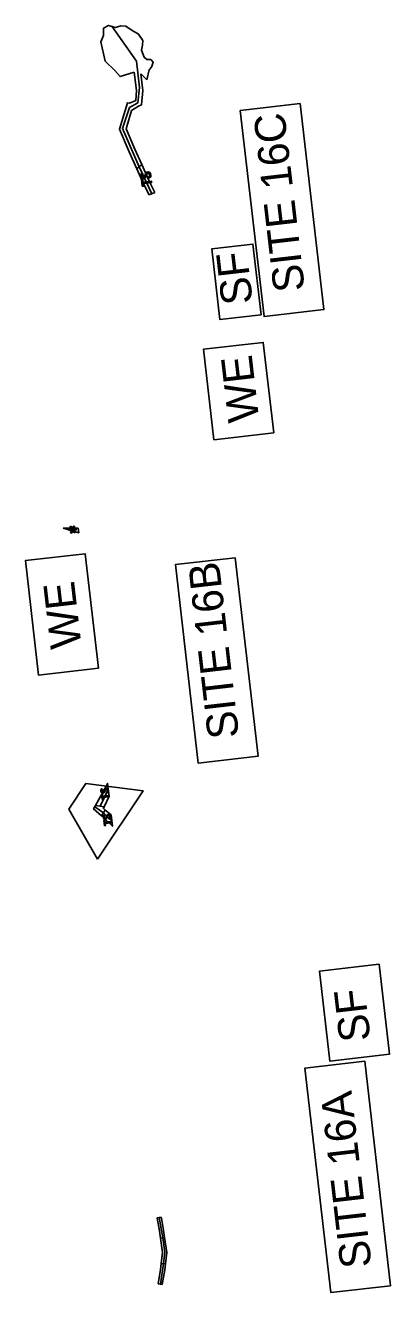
# Model space of a CAD drawing. Extents: x 474218 to 481634, y 484357 to 504997.
# Drawn here: x 478282 to 478459, y 495986 to 496599 of the extents above; entities that cross this region are included whole.
import ezdxf

# ---------------------------------------------------------------- set-up
doc = ezdxf.new("R2010")
doc.units = 0
for name, color, linetype in [('Exist Hydro Jurisdictional Stream or Body of Water', 7, 'Continuous'), ('Old_Level_29', 7, 'Continuous'), ('Old_Level_30', 7, 'Continuous'), ('Prop Boundary Clearing Mechanized Hatching CELL', 7, 'Continuous'), ('Prop Earthen Structure Impacts In Surface Waters Hatching CELL', 7, 'Continuous'), ('Prop Grid Mask', 7, 'Continuous'), ('Scratch_Level_4', 7, 'Continuous'), ('Temp Earthen Structure Impacts In Surface Waters Hatching CELL', 7, 'Continuous')]:
    doc.layers.add(name, color=color, linetype=linetype)

msp = doc.modelspace()

# ---------------------------------------------------------------- linework, layer by layer
at = {"layer": 'Exist Hydro Jurisdictional Stream or Body of Water'}
for points in [[(478376.47, 496456.35), (478372.53, 496490.56), (478392.45, 496492.85), (478396.39, 496458.64)], [(478429.6, 496097.83), (478424.59, 496141.27), (478453.48, 496144.61), (478458.49, 496101.17)]]:
    msp.add_lwpolyline(points, close=True, dxfattribs=at)
at = {"layer": 'Old_Level_29'}
for points in [[(478397.84, 496457.83), (478386.35, 496557.43), (478415.25, 496560.76), (478426.74, 496461.16)], [(478366.04, 496241.85), (478354.97, 496337.87), (478383.87, 496341.2), (478394.94, 496245.18)], [(478430.14, 495985.85), (478417.61, 496094.47), (478446.51, 496097.8), (478459.04, 495989.18)]]:
    msp.add_lwpolyline(points, close=True, dxfattribs=at)
at = {"layer": 'Old_Level_30'}
for points in [[(478373.6, 496398.29), (478368.56, 496442.01), (478397.45, 496445.34), (478402.49, 496401.62)], [(478288.84, 496284.41), (478282.45, 496339.82), (478311.34, 496343.16), (478317.73, 496287.74)]]:
    msp.add_lwpolyline(points, close=True, dxfattribs=at)
at = {"layer": 'Prop Boundary Clearing Mechanized Hatching CELL'}
for p, q in [((478300.65, 496355.5), (478308.23, 496353.27)), ((478307.98, 496355.43), (478300.65, 496355.5)), ((478308.23, 496353.27), (478307.98, 496355.43))]:
    msp.add_line(p, q, dxfattribs=at)
for points in [[(478304.79, 496354.47), (478304.84, 496354.48), (478304.77, 496355.05), (478304.72, 496355.04), (478303.62, 496354.98), (478303.7, 496354.3)], [(478304.77, 496355.07), (478304.79, 496355.05), (478304.65, 496356.28), (478304.63, 496356.31), (478304.56, 496356.4), (478304.01, 496355.99), (478304.71, 496355.15)], [(478305.42, 496354.22), (478305.45, 496354.27), (478305.31, 496355.43), (478305.29, 496355.37), (478304.65, 496356.28), (478304.79, 496355.05), (478304.77, 496355.05), (478304.84, 496354.48), (478304.8, 496354.39), (478304.32, 496353.4), (478304.32, 496353.39), (478304.94, 496353.12), (478304.99, 496353.22), (478305, 496353.25)], [(478306.02, 496353.4), (478306.12, 496353.26), (478305.98, 496354.48), (478305.89, 496354.59), (478305.82, 496355.17), (478305.81, 496355.17), (478305.67, 496356.35), (478305.31, 496355.43), (478305.45, 496354.27), (478306.01, 496353.43)], [(478305.88, 496355.31), (478306.36, 496356.25), (478305.74, 496356.53), (478305.67, 496356.35), (478305.81, 496355.17)], [(478306.55, 496354.64), (478307.06, 496354.67), (478306.98, 496355.36), (478306.48, 496355.28), (478306.47, 496355.28), (478305.9, 496355.18), (478305.82, 496355.17), (478305.89, 496354.59), (478305.97, 496354.6), (478306.55, 496354.64)], [(478306.66, 496353.66), (478306.66, 496353.67), (478306.66, 496353.67), (478305.98, 496354.48), (478306.12, 496353.26)]]:
    msp.add_lwpolyline(points, close=True, dxfattribs=at)
at = {"layer": 'Prop Earthen Structure Impacts In Surface Waters Hatching CELL'}
for p, q in [((478338.24, 496575.16), (478341.19, 496572.34)), ((478333.82, 496557.47), (478337.16, 496559.59)), ((478336.34, 496529.2), (478338.68, 496531.3)), ((478349.76, 496012.52), (478347.78, 496012.24)), ((478348.15, 495999.88), (478350.16, 495999.86))]:
    msp.add_line(p, q, dxfattribs=at)
for points in [[(478341.19, 496572.34), (478342.33, 496577.12), (478343.44, 496578.45), (478344.2, 496580.76), (478343.07, 496582.04), (478341.17, 496582.07), (478339.84, 496583.18), (478338.66, 496586.7), (478339.05, 496589.05), (478339.25, 496591.23), (478337.2, 496594.43), (478333.53, 496596.42), (478331.09, 496598.22), (478328.54, 496598.45), (478326.03, 496597.51), (478322.68, 496598.62), (478320.17, 496597.2), (478320.15, 496593.76), (478318.87, 496590.61), (478321.06, 496581.27), (478325.78, 496576.8), (478328.26, 496573.82), (478335.11, 496575.92)], [(478335.11, 496575.92), (478336.25, 496567.12), (478335.81, 496562.27), (478332.74, 496560.94)], [(478337.16, 496559.59), (478338.63, 496560.22), (478339.27, 496567.18), (478338.24, 496575.16)], [(478332.74, 496560.94), (478331.83, 496561.22), (478327.95, 496548.46), (478332.63, 496537.53), (478336.34, 496529.2)], [(478338.68, 496531.3), (478335.38, 496538.74), (478331.14, 496548.63), (478333.82, 496557.47)], [(478333.82, 496557.47), (478333.82, 496557.47), (478333.82, 496557.47)], [(478337.16, 496559.59), (478337.16, 496559.59), (478337.16, 496559.59), (478337.16, 496559.59)], [(478319.27, 496216.43), (478321.11, 496219.19), (478320.19, 496219.93), (478320.6, 496220.83), (478316.32, 496221.36), (478315.44, 496219.76), (478319.27, 496216.43)], [(478347.78, 496012.24), (478348.78, 496005.25), (478348.15, 495999.88)], [(478350.16, 495999.86), (478350.8, 496005.28), (478349.76, 496012.52)]]:
    msp.add_lwpolyline(points, dxfattribs=at)
at = {"layer": 'Prop Grid Mask'}
for points in [[(478426.74, 496461.16), (478415.25, 496560.76), (478386.35, 496557.43), (478397.84, 496457.83)], [(478396.39, 496458.64), (478392.45, 496492.85), (478372.53, 496490.56), (478376.47, 496456.35)], [(478402.49, 496401.62), (478397.45, 496445.34), (478368.56, 496442.01), (478373.6, 496398.29)], [(478317.73, 496287.74), (478311.34, 496343.16), (478282.45, 496339.82), (478288.84, 496284.41)], [(478394.94, 496245.18), (478383.87, 496341.2), (478354.97, 496337.87), (478366.04, 496241.85)], [(478458.49, 496101.17), (478453.48, 496144.61), (478424.59, 496141.27), (478429.6, 496097.83)], [(478459.04, 495989.18), (478446.51, 496097.8), (478417.61, 496094.47), (478430.14, 495985.85)]]:
    msp.add_lwpolyline(points, close=True, dxfattribs=at)
at = {"layer": 'Scratch_Level_4'}
for p, q in [((478336.21, 496581.35), (478324.23, 496598.15)), ((478337.71, 496568.53), (478336.21, 496581.35)), ((478343.61, 496517.22), (478337.45, 496530.22)), ((478318.58, 496221.07), (478322.52, 496229.19)), ((478315.96, 496220.72), (478320.18, 496217.82)), ((478320.18, 496217.82), (478324.28, 496213.88)), ((478348.87, 496012.39), (478347.13, 496022.19)), ((478347.73, 495989.97), (478349.21, 495999.87))]:
    msp.add_line(p, q, dxfattribs=at)
for points in [[(478337.45, 496530.22), (478329.4, 496548.75), (478332.81, 496558.84), (478336.78, 496561.1), (478337.71, 496568.53)], [(478349.21, 495999.87), (478349.8, 496005.44), (478348.87, 496012.39)]]:
    msp.add_lwpolyline(points, dxfattribs=at)
for points in [[(478300.65, 496355.5), (478308.23, 496353.27), (478307.98, 496355.43)], [(478317.26, 496195.39), (478339.37, 496228.56), (478311.64, 496232.03), (478303.4, 496219.66)], [(478319.27, 496216.43), (478321.11, 496219.19), (478320.19, 496219.93), (478320.6, 496220.83), (478316.32, 496221.36), (478315.44, 496219.76)]]:
    msp.add_lwpolyline(points, close=True, dxfattribs=at)
at = {"layer": 'Temp Earthen Structure Impacts In Surface Waters Hatching CELL'}
for p, q in [((478338.68, 496531.3), (478336.34, 496529.2)), ((478342.25, 496516.6), (478344.98, 496517.84)), ((478349.76, 496012.52), (478349.13, 496016.99)), ((478347.78, 496012.24), (478349.76, 496012.52))]:
    msp.add_line(p, q, dxfattribs=at)
for points in [[(478344.98, 496517.84), (478342.24, 496523.3), (478338.68, 496531.3)], [(478336.34, 496529.2), (478339.53, 496522.02), (478342.25, 496516.6)], [(478316.32, 496221.36), (478320.6, 496220.83), (478322.89, 496225.95), (478322.19, 496232.07), (478321.44, 496230.72), (478316.32, 496221.36)], [(478319.27, 496216.43), (478320.78, 496215.12), (478324.57, 496211.37), (478323.94, 496216.84), (478321.11, 496219.19), (478319.27, 496216.43)], [(478349.13, 496016.99), (478348.39, 496020.84), (478348.1, 496022.35), (478346.13, 496022.02), (478346.35, 496020.86), (478347.15, 496016.66), (478347.78, 496012.24)], [(478348.65, 495989.81), (478349.81, 495996.83), (478350.16, 495999.86), (478348.15, 495999.88), (478347.83, 495997.11), (478346.68, 495990.14), (478348.65, 495989.81)]]:
    msp.add_lwpolyline(points, dxfattribs=at)
for points in [[(478338.41, 496525.35), (478338.43, 496525.29), (478338.29, 496526.45), (478338.29, 496526.43), (478338.27, 496525.85), (478338.27, 496525.84)], [(478339.84, 496524.63), (478340.01, 496524.67), (478339.91, 496525.55), (478339.75, 496525.43), (478339.5, 496525.38), (478339.48, 496525.38), (478339.42, 496525.39), (478339.24, 496525.44), (478339.17, 496525.5), (478339.09, 496525.58), (478339.04, 496525.62), (478339.03, 496525.65), (478338.99, 496525.77), (478338.93, 496525.91), (478338.78, 496527.21), (478338.71, 496527.16), (478338.5, 496526.92), (478338.45, 496526.87), (478338.29, 496526.45), (478338.43, 496525.29), (478338.67, 496524.97), (478338.73, 496524.89), (478338.99, 496524.74), (478339.07, 496524.69), (478339.11, 496524.67), (478339.15, 496524.65), (478339.16, 496524.65), (478339.19, 496524.64), (478339.27, 496524.63), (478339.33, 496524.62), (478339.51, 496524.6), (478339.57, 496524.59), (478339.59, 496524.58)], [(478338.96, 496520.8), (478339.61, 496520.87), (478339.24, 496524.09), (478338.59, 496524.02)], [(478339.11, 496526.56), (478339.26, 496526.72), (478339.06, 496527.03), (478338.99, 496527.13), (478338.89, 496527.27), (478338.86, 496527.25), (478338.85, 496527.25), (478338.82, 496527.23), (478338.78, 496527.21), (478338.93, 496525.91), (478338.93, 496526.25), (478338.96, 496526.3), (478338.96, 496526.31), (478338.99, 496526.38), (478339.06, 496526.51)], [(478340.28, 496524.83), (478340.37, 496524.89), (478340.23, 496526.13), (478340.16, 496525.9), (478339.99, 496525.6), (478339.91, 496525.55), (478340.01, 496524.66), (478340.09, 496524.71)], [(478342.38, 496526.59), (478342.46, 496526.3), (478342.31, 496527.6), (478342.26, 496527.63), (478342.25, 496527.63), (478342.24, 496527.64), (478342.14, 496527.69), (478342.1, 496527.69), (478342.08, 496527.69), (478341.94, 496527.71), (478341.87, 496527.71), (478341.83, 496527.72), (478341.65, 496527.73), (478341.54, 496527.71), (478341.28, 496527.65), (478341.16, 496527.63), (478341.08, 496527.56), (478340.91, 496527.44), (478340.91, 496527.44), (478340.78, 496527.35), (478340.7, 496527.22), (478340.51, 496526.9), (478340.47, 496526.8), (478340.3, 496526.36), (478340.23, 496526.13), (478340.37, 496524.89), (478340.46, 496525), (478340.65, 496525.24), (478340.69, 496525.33), (478340.87, 496525.74), (478340.95, 496525.93), (478341.05, 496526.24), (478341.19, 496526.6), (478341.27, 496526.7), (478341.37, 496526.83), (478341.63, 496526.94), (478341.74, 496526.94), (478341.92, 496526.95), (478341.97, 496526.93), (478342.03, 496526.9), (478342.17, 496526.85), (478342.21, 496526.81), (478342.25, 496526.75), (478342.36, 496526.62), (478342.37, 496526.6)], [(478343.13, 496525.7), (478343.16, 496526.35), (478342.98, 496526.99), (478342.98, 496527), (478342.64, 496527.41), (478342.6, 496527.46), (478342.31, 496527.6), (478342.46, 496526.3), (478342.45, 496525.94), (478342.45, 496525.94), (478342.44, 496525.91), (478342.37, 496525.72), (478342.34, 496525.65), (478342.31, 496525.62), (478342.19, 496525.49), (478342.14, 496525.44), (478342.09, 496525.42), (478341.93, 496525.33), (478342.14, 496524.97), (478342.2, 496524.88), (478342.27, 496524.76), (478342.41, 496524.82), (478342.43, 496524.83), (478342.47, 496524.85), (478342.56, 496524.89), (478342.57, 496524.9), (478342.57, 496524.9), (478342.62, 496524.94), (478342.86, 496525.16), (478342.89, 496525.19), (478343.13, 496525.69)], [(478339.47, 496522.1), (478343.47, 496522.57), (478343.38, 496523.32), (478339.38, 496522.86)], [(478320.12, 496227.36), (478320.24, 496227.39), (478320.16, 496228.09), (478320.05, 496228), (478319.87, 496227.96), (478319.85, 496227.96), (478319.81, 496227.97), (478319.68, 496228.01), (478319.64, 496228.06), (478319.57, 496228.13), (478319.54, 496228.16), (478319.53, 496228.19), (478319.5, 496228.28), (478319.46, 496228.4), (478319.34, 496229.43), (478319.29, 496229.4), (478319.14, 496229.21), (478319.11, 496229.16), (478319, 496228.83), (478319.11, 496227.9), (478319.28, 496227.65), (478319.33, 496227.58), (478319.51, 496227.46), (478319.57, 496227.42), (478319.6, 496227.4), (478319.63, 496227.38), (478319.63, 496227.38), (478319.66, 496227.38), (478319.72, 496227.37), (478319.76, 496227.36), (478319.88, 496227.34), (478319.93, 496227.33), (478319.94, 496227.33)], [(478319.1, 496227.95), (478319.11, 496227.91), (478319, 496228.83), (478319, 496228.82), (478319, 496228.35), (478319, 496228.35)], [(478319.54, 496224.3), (478320, 496224.36), (478319.7, 496226.94), (478319.24, 496226.88)], [(478319.58, 496228.91), (478319.69, 496229.04), (478319.54, 496229.28), (478319.49, 496229.37), (478319.42, 496229.48), (478319.39, 496229.47), (478319.39, 496229.46), (478319.37, 496229.45), (478319.34, 496229.43), (478319.46, 496228.4), (478319.46, 496228.66), (478319.47, 496228.7), (478319.48, 496228.72), (478319.5, 496228.77), (478319.54, 496228.87)], [(478319.88, 496225.34), (478322.71, 496225.67), (478322.64, 496226.27), (478319.81, 496225.95)], [(478320.43, 496227.51), (478320.49, 496227.56), (478320.38, 496228.56), (478320.33, 496228.37), (478320.21, 496228.14), (478320.16, 496228.09), (478320.24, 496227.39), (478320.29, 496227.42)], [(478321.89, 496228.9), (478321.95, 496228.67), (478321.83, 496229.71), (478321.79, 496229.73), (478321.79, 496229.73), (478321.78, 496229.74), (478321.71, 496229.78), (478321.69, 496229.78), (478321.66, 496229.79), (478321.57, 496229.8), (478321.52, 496229.8), (478321.49, 496229.81), (478321.36, 496229.82), (478321.28, 496229.8), (478321.1, 496229.76), (478321.02, 496229.74), (478320.96, 496229.69), (478320.85, 496229.6), (478320.85, 496229.6), (478320.75, 496229.52), (478320.7, 496229.42), (478320.57, 496229.17), (478320.54, 496229.09), (478320.43, 496228.74), (478320.38, 496228.56), (478320.49, 496227.56), (478320.55, 496227.65), (478320.68, 496227.84), (478320.71, 496227.91), (478320.84, 496228.23), (478320.88, 496228.39), (478320.96, 496228.63), (478321.05, 496228.92), (478321.11, 496229), (478321.18, 496229.1), (478321.36, 496229.19), (478321.43, 496229.19), (478321.56, 496229.19), (478321.6, 496229.17), (478321.64, 496229.15), (478321.74, 496229.11), (478321.77, 496229.07), (478321.8, 496229.03), (478321.88, 496228.93), (478321.89, 496228.91)], [(478322.43, 496228.18), (478322.45, 496228.7), (478322.31, 496229.22), (478322.31, 496229.22), (478322.07, 496229.55), (478322.04, 496229.59), (478321.83, 496229.71), (478321.95, 496228.67), (478321.95, 496228.38), (478321.95, 496228.38), (478321.94, 496228.36), (478321.89, 496228.21), (478321.87, 496228.15), (478321.86, 496228.13), (478321.77, 496228.03), (478321.73, 496227.98), (478321.7, 496227.96), (478321.59, 496227.9), (478321.74, 496227.61), (478321.78, 496227.53), (478321.84, 496227.44), (478321.93, 496227.48), (478321.95, 496227.49), (478321.97, 496227.51), (478322.04, 496227.54), (478322.04, 496227.55), (478322.05, 496227.55), (478322.08, 496227.58), (478322.25, 496227.75), (478322.27, 496227.78), (478322.43, 496228.17)], [(478320.27, 496215.29), (478320.28, 496215.24), (478320.18, 496216.17), (478320.17, 496216.15), (478320.17, 496215.69), (478320.17, 496215.68)], [(478321.29, 496214.7), (478321.41, 496214.72), (478321.33, 496215.43), (478321.22, 496215.33), (478321.04, 496215.3), (478321.03, 496215.3), (478320.98, 496215.31), (478320.86, 496215.35), (478320.81, 496215.4), (478320.74, 496215.47), (478320.72, 496215.5), (478320.71, 496215.52), (478320.67, 496215.62), (478320.63, 496215.73), (478320.51, 496216.77), (478320.46, 496216.73), (478320.32, 496216.54), (478320.28, 496216.5), (478320.18, 496216.17), (478320.28, 496215.24), (478320.46, 496214.98), (478320.5, 496214.91), (478320.68, 496214.79), (478320.75, 496214.75), (478320.78, 496214.73), (478320.8, 496214.72), (478320.81, 496214.72), (478320.83, 496214.71), (478320.89, 496214.7), (478320.93, 496214.69), (478321.05, 496214.67), (478321.1, 496214.66), (478321.11, 496214.66)], [(478320.71, 496211.64), (478321.17, 496211.69), (478320.87, 496214.27), (478320.41, 496214.22)], [(478320.75, 496216.25), (478320.86, 496216.37), (478320.71, 496216.62), (478320.66, 496216.7), (478320.59, 496216.82), (478320.56, 496216.8), (478320.56, 496216.8), (478320.54, 496216.79), (478320.51, 496216.77), (478320.63, 496215.73), (478320.63, 496216), (478320.65, 496216.04), (478320.65, 496216.05), (478320.67, 496216.1), (478320.72, 496216.21)], [(478321.05, 496212.68), (478323.88, 496213.01), (478323.81, 496213.61), (478320.98, 496213.28)], [(478321.6, 496214.85), (478321.66, 496214.9), (478321.55, 496215.9), (478321.5, 496215.71), (478321.38, 496215.47), (478321.33, 496215.43), (478321.41, 496214.72), (478321.46, 496214.76)], [(478323.06, 496216.23), (478323.13, 496216), (478323.01, 496217.05), (478322.97, 496217.07), (478322.97, 496217.07), (478322.96, 496217.07), (478322.88, 496217.12), (478322.86, 496217.12), (478322.84, 496217.12), (478322.74, 496217.13), (478322.7, 496217.14), (478322.66, 496217.14), (478322.53, 496217.16), (478322.46, 496217.14), (478322.27, 496217.1), (478322.19, 496217.08), (478322.13, 496217.03), (478322.02, 496216.93), (478322.02, 496216.93), (478321.93, 496216.86), (478321.87, 496216.76), (478321.74, 496216.51), (478321.71, 496216.43), (478321.6, 496216.08), (478321.55, 496215.9), (478321.66, 496214.9), (478321.72, 496214.98), (478321.86, 496215.17), (478321.88, 496215.24), (478322.01, 496215.57), (478322.06, 496215.73), (478322.13, 496215.97), (478322.22, 496216.26), (478322.28, 496216.34), (478322.35, 496216.44), (478322.53, 496216.53), (478322.61, 496216.53), (478322.73, 496216.53), (478322.77, 496216.51), (478322.81, 496216.49), (478322.92, 496216.44), (478322.94, 496216.41), (478322.97, 496216.37), (478323.05, 496216.26), (478323.06, 496216.25)], [(478323.61, 496215.51), (478323.62, 496216.03), (478323.49, 496216.55), (478323.48, 496216.56), (478323.24, 496216.89), (478323.21, 496216.93), (478323.01, 496217.05), (478323.13, 496216), (478323.12, 496215.72), (478323.12, 496215.71), (478323.12, 496215.69), (478323.07, 496215.54), (478323.05, 496215.49), (478323.03, 496215.46), (478322.94, 496215.36), (478322.91, 496215.32), (478322.87, 496215.3), (478322.76, 496215.23), (478322.92, 496214.95), (478322.96, 496214.87), (478323.01, 496214.77), (478323.1, 496214.82), (478323.12, 496214.83), (478323.15, 496214.84), (478323.21, 496214.87), (478323.22, 496214.88), (478323.22, 496214.88), (478323.25, 496214.92), (478323.42, 496215.09), (478323.44, 496215.11), (478323.61, 496215.51)]]:
    msp.add_lwpolyline(points, close=True, dxfattribs=at)

# ---------------------------------------------------------------- texts
at = {"layer": 'Exist Hydro Jurisdictional Stream or Body of Water'}
for p in [(478392.44, 496464.44), (478449.38, 496108.05)]:
    msp.add_text('SF', height=15, rotation=96.57763, dxfattribs=at).set_placement(p)
at = {"layer": 'Old_Level_29'}
for s, p in [('SITE 16C', (478417.59, 496470.58)), ('SITE 16B', (478385.8, 496254.59)), ('SITE 16A', (478449.89, 495998.6))]:
    msp.add_text(s, height=15, rotation=96.57763, dxfattribs=at).set_placement(p)
at = {"layer": 'Old_Level_30'}
for p in [(478395.53, 496407.65), (478309.65, 496298.23)]:
    msp.add_text('WE', height=15, rotation=96.57763, dxfattribs=at).set_placement(p)

doc.saveas('drawing.dxf')
